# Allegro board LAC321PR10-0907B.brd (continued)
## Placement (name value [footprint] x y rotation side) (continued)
CC88  0.1U_0201_10V6K  [C_0201]  120.38 115.51 270 top
CC89  0.1U_0201_10V6K  [C_0201]  128.61 110.87 270 bottom
CC90  0.1U_0201_10V6K  [C_0201]  127.79 110.87 270 bottom
CC91  0.1U_0201_10V6K  [C_0201]  127.06 110.87 270 bottom
CC92  0.1U_0201_10V6K  [C_0201]  126.08 108.47 180 bottom
CC93  0.1U_0201_10V6K  [C_0201]  126.08 107.91 180 bottom
CC94  0.1U_0201_10V6K  [C_0201]  124.82 107.16 270 bottom
CC95  0.1U_0201_10V6K  [C_0201]  126.08 105.67 180 bottom
CC96  0.1U_0201_10V6K  [C_0201]  126.08 106.23 180 bottom
CC97  0.1U_0201_10V6K  [C_0201]  126.08 106.79 180 bottom
CC98  0.1U_0201_10V6K  [C_0201]  126.08 107.35 180 bottom
CC99  0.1U_0201_10V6K  [C_0201]  124.82 108.33 270 bottom
CC100  0.1U_0201_10V6K  [C_0201]  126.08 105.11 180 bottom
CC101  0.1U_0201_10V6K  [C_0201]  126.08 104.55 180 bottom
CC102  0.1U_0201_10V6K  [C_0201]  124.82 105.41 90 bottom
CC103  0.1U_0201_10V6K  [C_0201]  124.82 104.24 90 bottom
CC104  0.1U_0201_10V6K  [C_0201]  124.34 109.62 270 bottom
CC105  0.1U_0201_10V6K  [C_0201]  120.07 109.65 270 bottom
CC106  0.1U_0201_10V6K  [C_0201]  118.85 109.65 270 bottom
CC107  0.1U_0201_10V6K  [C_0201]  119.46 109.65 270 bottom
CC108  0.1U_0201_10V6K  [C_0201]  125.56 109.62 270 bottom
CC109  0.1U_0201_10V6K  [C_0201]  123.12 109.65 270 bottom
CC110  0.1U_0201_10V6K  [C_0201]  122.51 109.65 270 bottom
CC111  0.1U_0201_10V6K  [C_0201]  128.66 109.62 270 bottom
CC112  0.1U_0201_10V6K  [C_0201]  129.09 107.42 0 bottom
CC113  0.1U_0201_10V6K  [C_0201]  129.09 106.87 0 bottom
CC114  0.1U_0201_10V6K  [C_0201]  129.09 106.31 0 bottom
CC115  0.1U_0201_10V6K  [C_0201]  129.09 105.75 0 bottom
CC116  0.1U_0201_10V6K  [C_0201]  129.09 104.63 0 bottom
CC117  1U_0402_6.3V6K  [C_0402]  116.95 116.8 90 top
CC118  22U_0603_6.3V6M  [C_0603]  118.22 116.68 90 top
CC119  0.1U_0201_10V6K  [C_0201]  129.09 105.19 0 bottom
CC120  0.1U_0201_10V6K  [C_0201]  127.39 109.62 270 bottom
CC121  0.1U_0201_10V6K  [C_0201]  126.78 109.62 270 bottom
CC122  0.1U_0201_10V6K  [C_0201]  128 109.62 270 bottom
CC123  0.1U_0201_10V6K  [C_0201]  121.29 109.65 270 bottom
CC124  0.1U_0201_10V6K  [C_0201]  123.73 109.65 270 bottom
CC125  0.1U_0201_10V6K  [C_0201]  120.68 109.65 270 bottom
CC126  0.1U_0201_10V6K  [C_0201]  121.9 109.65 270 bottom
CC127  0.1U_0201_10V6K  [C_0201]  124.95 109.62 270 bottom
CC128  0.1U_0201_10V6K  [C_0201]  126.17 109.62 270 bottom
CC129  0.1U_0201_10V6K  [C_0201]  130.5 104.43 0 bottom
CC130  0.1U_0201_10V6K  [C_0201]  132.4 107.98 0 bottom
CC131  0.1U_0201_10V6K  [C_0201]  132.53 106.33 0 bottom
CC132  0.1U_0201_10V6K  [C_0201]  131.9 101.38 0 bottom
CC133  22U_0603_6.3V6M  [C_0603]  140.13 92.87 180 top
CC134  0.1U_0201_10V6K  [C_0201]  131.9 100.74 0 bottom
CC135  0.1U_0201_10V6K  [C_0201]  131.78 102.01 0 bottom
CC158  0.1U_0201_10V6K  [C_0201]  137.52 104.64 90 top
CC161  0.1U_0201_10V6K  [C_0201]  118.94 88.52 270 top
CC162  0.1U_0201_10V6K  [C_0201]  121.77 93.54 270 top
CC163  0.1U_0201_10V6K  [C_0201]  146.03 95.91 90 top
CC164  10P_0201_25V8  [C_0201]  139.02 110.32 180 top
CH3  15P_0402_50V8J  [C_0402]  141.89 97.43 270 top
CH4  15P_0402_50V8J  [C_0402]  141.71 99.17 270 top
CH5  1U_0402_6.3V6K  [C_0402]  139.91 116.82 270 top
CH6  1U_0402_6.3V6K  [C_0402]  142.58 119.85 90 top
CH7  10P_0402_50V8J  [C_0402]  139.05 119.72 90 top
CH8  8P_0402_50V8D  [C_0402]  139.08 118.78 270 top
CH11  0.22U_0201_6.3V6M  [C_0201]  135.81 92.59 90 top
CH12  0.22U_0201_6.3V6M  [C_0201]  136.38 92.59 90 top
CH13  0.22U_0201_6.3V6M  [C_0201]  133.84 93.8 90 top
CH14  0.22U_0201_6.3V6M  [C_0201]  134.41 93.8 90 top
CH16  0.22U_0201_6.3V6M  [C_0201]  135.12 93.86 90 top
CH17  0.22U_0201_6.3V6M  [C_0201]  135.69 93.87 90 top
CH19  0.22U_0201_6.3V6M  [C_0201]  134.51 92.61 90 top
CH20  0.22U_0201_6.3V6M  [C_0201]  135.08 92.6 90 top
CH21  0.1U_0201_10V6K  [C_0201]  131.03 94.34 90 top
CH22  0.1U_0201_10V6K  [C_0201]  131.6 94.34 90 top
CH23  0.22U_0201_6.3V6M  [C_0201]  197 92.11 180 bottom
CH24  0.22U_0201_6.3V6M  [C_0201]  197 92.74 180 bottom
CH25  0.22U_0201_6.3V6M  [C_0201]  197 89.57 180 bottom
CH26  0.22U_0201_6.3V6M  [C_0201]  197 90.2 180 bottom
CH27  0.1U_0201_10V6K  [C_0201]  130.54 92.58 90 top
CH28  0.1U_0201_10V6K  [C_0201]  131.15 92.58 90 top
CH32  0.1U_0201_10V6K  [C_0201]  212.07 135 90 top
CH35  0.22U_0201_6.3V6M  [C_0201]  132.45 93.95 90 top
CH36  0.22U_0201_6.3V6M  [C_0201]  133.03 93.96 90 top
CH39  0.1U_0201_10V6K  [C_0201]  138.25 128.57 0 top
CH40  0.1U_0201_10V6K  [C_0201]  139.19 122.06 0 top
CH41  0.1U_0201_10V6K  [C_0201]  141.55 110.4 0 bottom
CH42  0.1U_0201_10V6K  [C_0201]  140.79 112.81 0 bottom
CH43  0.1U_0201_10V6K  [C_0201]  164.27 108.9 0 top
CH44  0.1U_0201_10V6K  [C_0201]  241.98 105.84 90 top
CH45  0.1U_0201_10V6K  [C_0201]  242.55 105.84 90 top
CH46  0.1U_0201_10V6K  [C_0201]  144.34 119.54 0 top
CH47  0.1U_0201_10V6K  [C_0201]  130.26 84.7 180 top
CH48  0.1U_0201_10V6K  [C_0201]  130.26 84.15 180 top
CH49  0.1U_0201_10V6K  [C_0201]  144.51 125.29 0 top
CH50  0.1U_0201_10V6K  [C_0201]  139.87 122.77 180 top
CLRP3  SHORT PADS  [SHORTPADS]  160.36 132.8 270 top
CLRP4  SHORT PADS  [SHORTPADS]  142.6 118.27 90 top
CR1  1U_0201_6.3V6M  [C_0201]  23.43 80.59 0 top
CR2  10U_0402_6.3V6M  [C_0402]  28.81 84.36 180 top
CR3  0.1U_0201_10V6K  [C_0201]  28.81 83.6 180 top
CR4  0.1U_0201_10V6K  [C_0201]  29.94 84.44 270 top
CR5  0.1U_0201_10V6K  [C_0201]  27.15 83.85 90 top
CR6  4.7U_0402_6.3V6M  [C_0402]  26.38 83.69 90 top
CR7  0.1U_0201_10V6K  [C_0201]  27.15 75.55 270 top
CR8  2.2P_0402_50V8C~D  [C_0402]  23.72 82.04 90 top
CR11  4.7U_0402_6.3V6M  [C_0402]  26.4 75.62 270 top
CR14  10U_0402_6.3V6M  [C_0402]  21.82 82.71 90 top
CR15  0.1U_0201_10V6K  [C_0201]  22.55 82.65 90 top
CR16  1U_0201_6.3V6M  [C_0201]  23.43 76.15 0 top
CR17  4.7U_0402_6.3V6M  [C_0402]  21.82 86.06 90 top
CR18  0.1U_0201_10V6K  [C_0201]  21.7 85.29 270 top
CR19  6.8P_0201_25V8B  [C_0201]  23.43 76.78 0 top
CR20  6.8P_0201_25V8B  [C_0201]  23.43 78.05 0 top
CR21  6.8P_0201_25V8B  [C_0201]  23.43 79.37 0 top
CR22  0.1U_0201_10V6K  [C_0201]  23.72 84.44 270 top
CR23  6.8P_0201_25V8B  [C_0201]  24.99 84.44 270 top
CT1  10U_0603_25V6M  [C_0603]  15.49 37.03 270 top
CT2  10U_0603_25V6M  [C_0603]  13.63 18.45 0 top
CT3  0.1U_0402_25V6  [C_0402]  9.02 23.99 270 top
CT4  0.1U_0402_25V6  [C_0402]  10.8 21.32 90 top
D1  -  [BAT54CW-7-F_SOT323-3]  174.43 104.12 0 top
D2  -  [BAT54CW-7-F_SOT323-3]  176.84 102.22 180 top
D3  -  [BAT54CW-7-F_SOT323-3]  179.25 102.22 180 top
D4  -  [PJSOT24CW_SOT323-3]  240.26 122.65 180 top
D5  -  [PJSOT24CW_SOT323-3]  222.64 124.39 180 top
D6  -  [AOZ8904CIL_SOT23-6]  25.67 73.12 180 top
D8  -  [BAT54A-7-F_SOT23-3]  38.19 11.46 90 top
D10  -  [BAT54CW-7-F_SOT323-3]  232.2 136.48 270 top
D11  -  [BAT54CW-7-F_SOT323-3]  37.51 95.26 0 top
D17  -  [PESD24VS2UT_SOT23-3]  92.08 90.46 180 top
D22  -  [SDMK0340L-7-F_SOD323-2]  229.17 133.87 180 top
D23  -  [SDMK0340L-7-F_SOD323-2]  204.58 109.22 90 top
D74  -  [TPD2EUSB30DRTR_SOT3]  126.24 87.58 270 top
D75  ESD8011MUT5G X3DFN2  [ESD101-B1-02ELS_TSSLP-2-4-2]  12.45 36.8 90 bottom
D76  ESD8011MUT5G X3DFN2  [ESD101-B1-02ELS_TSSLP-2-4-2]  12.36 31.41 225 bottom
D77  ESD8011MUT5G X3DFN2  [ESD101-B1-02ELS_TSSLP-2-4-2]  13.41 36.8 90 bottom
D78  ESD8011MUT5G X3DFN2  [ESD101-B1-02ELS_TSSLP-2-4-2]  11.73 32.17 225 bottom
D79  ESD8011MUT5G X3DFN2  [ESD101-B1-02ELS_TSSLP-2-4-2]  10.61 35.78 90 bottom
D80  ESD8011MUT5G X3DFN2  [ESD101-B1-02ELS_TSSLP-2-4-2]  12.64 29.06 225 bottom
D81  ESD8011MUT5G X3DFN2  [ESD101-B1-02ELS_TSSLP-2-4-2]  11.57 35.78 90 bottom
D82  ESD8011MUT5G X3DFN2  [ESD101-B1-02ELS_TSSLP-2-4-2]  12 29.83 225 bottom
D83  ESD8011MUT5G X3DFN2  [ESD101-B1-02ELS_TSSLP-2-4-2]  11.78 22.51 90 bottom
D84  ESD8011MUT5G X3DFN2  [ESD101-B1-02ELS_TSSLP-2-4-2]  14.17 24.77 270 bottom
D85  ESD8011MUT5G X3DFN2  [ESD101-B1-02ELS_TSSLP-2-4-2]  12.77 22.51 90 bottom
D86  ESD8011MUT5G X3DFN2  [ESD101-B1-02ELS_TSSLP-2-4-2]  13.18 24.77 270 bottom
D87  ESD8011MUT5G X3DFN2  [ESD101-B1-02ELS_TSSLP-2-4-2]  10.37 24.39 90 bottom
D88  ESD8011MUT5G X3DFN2  [ESD101-B1-02ELS_TSSLP-2-4-2]  15.77 23.39 270 bottom
D89  ESD8011MUT5G X3DFN2  [ESD101-B1-02ELS_TSSLP-2-4-2]  11.33 24.39 90 bottom
D90  ESD8011MUT5G X3DFN2  [ESD101-B1-02ELS_TSSLP-2-4-2]  14.78 23.39 270 bottom
D95  -  [L06ESDU5V0CE2_SOD-882-2]  72.88 148.63 90 top
D100  -  [SDMK0340L-7-F_SOD323-2]  32.86 32.85 90 top
D101  -  [SDMK0340L-7-F_SOD323-2]  31.62 52.78 90 top
D406  -  [RB520SM-30T2R_EMD2-2]  175.41 115.82 180 top
D407  ESD8011MUT5G X3DFN2  [ESD101-B1-02ELS_TSSLP-2-4-2]  13.6 33.78 90 top
D408  ESD8011MUT5G X3DFN2  [ESD101-B1-02ELS_TSSLP-2-4-2]  14.31 34.16 270 top
D409  ESD8011MUT5G X3DFN2  [ESD101-B1-02ELS_TSSLP-2-4-2]  13.84 29.29 180 top
D410  ESD8011MUT5G X3DFN2  [ESD101-B1-02ELS_TSSLP-2-4-2]  13.46 30.01 0 top
D411  ESD8011MUT5G X3DFN2  [ESD101-B1-02ELS_TSSLP-2-4-2]  13.46 28.57 0 top
D412  ESD8011MUT5G X3DFN2  [ESD101-B1-02ELS_TSSLP-2-4-2]  13.49 25.83 270 top
D413  ESD8011MUT5G X3DFN2  [ESD101-B1-02ELS_TSSLP-2-4-2]  13.49 26.46 90 top
D414  ESD8011MUT5G X3DFN2  [ESD101-B1-02ELS_TSSLP-2-4-2]  13.49 27.49 90 top
D415  ESD8011MUT5G X3DFN2  [ESD101-B1-02ELS_TSSLP-2-4-2]  15.87 18.02 90 top
D416  ESD8011MUT5G X3DFN2  [ESD101-B1-02ELS_TSSLP-2-4-2]  16.58 18.4 270 top
D417  ESD8011MUT5G X3DFN2  [ESD101-B1-02ELS_TSSLP-2-4-2]  15.64 15.41 270 top
D418  ESD8011MUT5G X3DFN2  [ESD101-B1-02ELS_TSSLP-2-4-2]  14.93 15.03 90 top
D419  ESD8011MUT5G X3DFN2  [ESD101-B1-02ELS_TSSLP-2-4-2]  14.12 22.04 180 top
D420  ESD8011MUT5G X3DFN2  [ESD101-B1-02ELS_TSSLP-2-4-2]  13.74 21.32 0 top
D421  ESD8011MUT5G X3DFN2  [ESD101-B1-02ELS_TSSLP-2-4-2]  14.17 15.17 270 top
D422  ESD8011MUT5G X3DFN2  [ESD101-B1-02ELS_TSSLP-2-4-2]  13.46 15.17 270 top
D423  ESD207-B1-02ELE6327 TSLP-2-19  [ESD101-B1-02ELS_TSSLP-2-4-2]  191.66 96.76 0 top
D424  ESD218-B1-02ELS TSSLP-2-4  [ESD3V3S1B-02LS_PG-TSSLP-2-1-2]  15.45 37.92 0 top
D425  ESD218-B1-02ELS TSSLP-2-4  [ESD3V3S1B-02LS_PG-TSSLP-2-1-2]  13.67 22.83 0 top
DA1  -  [ESD207-B1-02EL_TSLP-2-19-2]  23.09 11.9 90 top
DA2  -  [ESD207-B1-02EL_TSLP-2-19-2]  15.23 96.93 90 top
DA3  -  [ESD207-B1-02EL_TSLP-2-19-2]  19.48 9.94 0 top
DA4  -  [ESD207-B1-02EL_TSLP-2-19-2]  21.83 9.94 180 top
DA5  -  [TVNST52302AB0_SOT523-3]  246.58 134.32 90 top
DA6  -  [TVNST52302AB0_SOT523-3]  23.36 92.9 270 top
DA7  -  [PJSOT24CW_SOT323-3]  37.34 25.28 180 top
DA8  -  [ESD207-B1-02EL_TSLP-2-19-2]  23.09 10.52 270 top
DH5  -  [RB751S40T1G_SOD523-2]  26.84 7.02 180 top
DH6  -  [RB751S40T1G_SOD523-2]  231.12 107.59 0 top
DI4  -  [TVNST52302AB0_SOT523-3]  186.48 96.3 90 top
DI5  -  [TVNST52302AB0_SOT523-3]  189.44 96.2 90 top
DI6  -  [PESD24VS2UT_SOT23-3]  19.84 55.74 180 top
DI7  BAT54A-7-F_SOT23-3  [PESD24VS2UT_SOT23-3]  36.18 40.01 0 top
FD1  -  [FIDUCIAL_C40M80]  249.09 143.39 0 top
FD2  -  [FIDUCIAL_C40M80]  14.76 11.07 0 top
FD3  -  [FIDUCIAL_C40M80]  14.84 11.55 90 bottom
FD4  -  [FIDUCIAL_C40M80]  243.57 147.89 90 bottom
H1  -  [H_4P6]  37.5 3.55 0 top
H2  -  [H_4P6]  194.5 83.55 90 top
H4  -  [H_4P6]  13.1 3.55 0 top
H5  -  [H_4P6]  43 147.55 0 top
H6  -  [H_4P6]  233.5 147.55 0 top
H7  -  [H_4P6]  7.5 108.05 0 top
H8  -  [H_1P2]  143.1 104.62 90 top
H9  -  [H_1P2]  104.1 103.62 90 top
H10  -  [H_1P3X2P3]  195.5 95.9 90 top
H11  -  [H_1P3]  3 95.9 0 top
H13  -  [H_2P0X0P4N]  160.5 138.5 0 top
H14  -  [H_2P0X0P4N]  147.7 126.11 90 top
H15  -  [H_2P0X0P4N]  103 131.05 0 top
H16  -  [H_2P0X0P4N]  63.95 126.31 90 top
H17  -  [H_2P0X0P4N]  68.15 130.7 0 top
H18  -  [H_2P0X0P4N]  197.49 103.09 90 top
H19  -  [H_2P0X0P4N]  143 131.05 0 top
H20  -  [H_2P0X0P4N]  92.85 130.7 0 top
H21  -  [H_2P0X0P4N]  152.5 131.55 0 top
H22  -  [H_2P0X0P4N]  181.5 138.5 0 top
H23  -  [H_4P6]  41.25 78.33 0 top
H24  -  [H_5P2]  139.1 78.33 0 top
H25  -  [H_2P0X0P4N]  40.46 58.96 270 top
H26  -  [H_2P0X0P4N]  12.24 10.66 270 top
H27  -  [H_2P0X0P4N]  4.67 45.42 270 top
H28  -  [H_2P0X0P4N]  20.37 62.59 270 top
H29  -  [H_2P0X0P4N]  56.85 83.74 0 top
H30  -  [H_2P0X0P4N]  49.64 150.07 0 top
H31  -  [H_2P0X0P4N]  40.81 142.09 0 top
H32  -  [H_2P0X0P4N]  241.88 140.61 0 top
H33  -  [H_2P0X0P4N]  242.21 113.41 0 top
H34  -  [H_2P0X0P4N]  199.26 113.41 0 top
J3  HRS_DF40C-24DS-0P4V(51)  [HRS_DF40C-24DS-0P4V-51_24P-T]  129.64 133.64 180 top
JANT1  BELLW_10093-1021  [BELLW_10093-1021_4P]  76.5 148.02 180 top
JAPS2  ACES_50506-01841-P01  [ACES_50506-01841-P01_18P]  224.77 143.67 180 top
JAR1  ACES_50281-00601-001  [ACES_50281-00601-001_6P]  34.02 47.07 90 top
JBAT100  ACES_50278-01001-001  [ACES_50278-01001-001_10P]  149.8 90.74 0 top
JCAM2  STARC_111D10-000000-G4-R  [STARC_111D10-000000-G4-R_10P]  99.34 132.71 180 top
JCR1  T-SOL_158-1000902614  [T-SOL_158-1000902614_23P-T]  17.15 83.22 270 top
JDEBUG1  ACES_50521-01041-P01  [ACES_50521-01041-P01_10P]  235.27 111.47 0 top
JDEG1  ACES_50521-01041-P01  [ACES_50521-01041-P01_10P]  211.73 146.22 180 top
JDMIC1  HRS_DF40B-12DS-0P4V(51)  [HRS_DF40B-12DS-0P4V-51_12P-T]  86.08 136.63 0 top
JHP1  ACES_50521-01041-P01  [ACES_50521-01041-P01_10P]  19.21 5.8 0 top
JITOUCH  ACES_50521-01041-P01  [ACES_50521-01041-P01_10P]  164.41 91.2 180 bottom
JLPDE1  ACES_50521-01041-P01  [ACES_50521-01041-P01_10P]  210.76 111.33 0 top
JLVDS1  ACES_50398-05071-001  [ACES_50398-05071-001_50P-T]  192.65 93.96 180 top
JNGFF1  LOTES_APCI0133-P001A  [LOTES_APCI0133-P001A_67P-T]  32.8 102.36 180 top
JNGFF2  LOTES_APCI0170-P001A  [LOTES_APCI0170-P001A_75P-T]  199.29 83.73 90 top
JNGFF3  LOTES_APCI0114-P001A  [LOTES_APCI0114-P001A_67P]  246.39 108.37 90 top
JP1  HRS_DF37NC-30DS-0P4V(51)  [HRS_DF37NC-30DS-0P4V-51_30P-T]  142.71 136.71 0 top
JPA1  0_0402_5%~D  [R0402_0OHM]  21.05 16.3 0 top
JPA2  0_0402_5%~D  [R0402_0OHM]  20.05 16.04 270 top
JPA3  0_0402_5%~D  [R0402_0OHM]  38.21 20.18 270 top
JPA4  0_0402_5%~D  [R_0402]  112.19 127.83 0 top
JPB1  ACES_50506-00641-P01  [ACES_50506-00641-P01_6P]  250.7 138.85 90 top
JPOGO  PANAS_AXT580124  [PANAS_AXT580124_80P-T]  107.7 86.23 0 top
JRTC1  ACES_50278-00201-001  [ACES_50278-00201-001_2P]  238.75 145.72 90 top
JSER  ACES_50506-01841-P01  [ACES_50506-01841-P01_18P]  220.65 138.59 0 bottom
JSIM1  JAE_SF56S006V4A  [JAE_SF56S006V4A_6P-T]  5.41 66.71 270 top
JSPI1  ACES_50696-0200M-P01  [ACES_50696-0200M-P01_20P]  214.28 140.64 0 bottom
JSPK1  ACES_50208-00201-P03  [ACES_50208-00201-P03_2P]  251.6 132.5 90 top
JSPK2  ACES_50208-00201-P03  [ACES_50208-00201-P03_2P]  10.8 96.89 270 top
JUSBC1  JAE_DX07B024XJ1  [JAE_DX07B024XJ1_24P-T]  8.66 33.26 270 top
JUSBC2  JAE_DX07B024XJ1  [JAE_DX07B024XJ1_24P-T]  8.66 19.26 270 top
JVB1  ACES_50208-00201-P03  [ACES_50208-00201-P03_2P]  28.95 5.5 0 top
JVOL1  ACES_50521-00541-P01  [ACES_50521-00541-P01_5P]  4.45 99.26 180 top
JXDP2  SAMTE_BSH-030-01-L-D-A-TR  [SAMTE_BSH-030-01-L-D-A-TR_60P-S]  108.05 91.8 0 bottom
L1  BLM15AX700SN1D_2P  [MURAT_BLM15AX100SN1D_2P]  26.67 10.7 180 top
L2  BLM15AX700SN1D_2P  [MURAT_BLM15AX100SN1D_2P]  26.67 11.72 180 top
L3  BLM15PX330SN1D_2P  [MURAT_BLM15PX330SN1D_2P]  21.32 11.97 0 top
L4  BLM15PX330SN1D_2P  [MURAT_BLM15PX330SN1D_2P]  20.1 11.97 180 top
L17  1UH_1269AS-H-1R0M-P2_2.5A_20%  [TOKO_1269AS-H-1R0M-P2_2P]  191.26 146.67 0 top
L19  FBMA-L11-160808-800LMT_0603  [KC_FBMA-L11-160808-800LMT_2P]  231.37 132.48 270 top
L21  10NH_LQG15HS10NJ02D_5%_0402  [MURAT_LQG15HS10NJ02D_2P]  72.88 147.57 270 top
L23  DLW21HN900HQ2L_4P  [MURAT_DLW21HN900HQ2L_4P]  106.32 127.58 90 top
L24  DLW21HN900HQ2L_4P  [MURAT_DLW21HN900HQ2L_4P]  143.7 127.53 90 top
L25  DLW21HN900HQ2L_4P  [MURAT_DLW21HN900HQ2L_4P]  194.46 99.43 0 top
L26  DLW21HN900HQ2L_4P  [MURAT_DLW21HN900HQ2L_4P]  239.24 120.58 0 top
L27  CMMI21T-900Y-N_4P  [CHILI_CMMI21T-900Y-N_4P]  16.12 98.13 0 top
L28  DLW21HN900HQ2L_4P  [MURAT_DLW21HN900HQ2L_4P]  108.23 127.58 90 top
L29  DLW21HN900HQ2L_4P  [MURAT_DLW21HN900HQ2L_4P]  104.42 127.58 90 top
L30  DLW21HN900HQ2L_4P  [MURAT_DLW21HN900HQ2L_4P]  158.74 134.2 180 top
L31  DLW21HN900HQ2L_4P  [MURAT_DLW21HN900HQ2L_4P]  145.59 127.52 90 top
L32  DLW21HN900HQ2L_4P  [MURAT_DLW21HN900HQ2L_4P]  158.74 132.3 180 top
L33  DLW21HN900HQ2L_4P  [MURAT_DLW21HN900HQ2L_4P]  158.74 136.11 180 top
L57  MCF12102G900-T_4P  [TAIYO_MCF12102G900-T_4P]  172.66 96.8 270 top
L58  MCF12102G900-T_4P  [TAIYO_MCF12102G900-T_4P]  174.18 96.8 270 top
L59  MCF12102G900-T_4P  [TAIYO_MCF12102G900-T_4P]  169.67 96.8 270 top
L60  MCF12102G900-T_4P  [TAIYO_MCF12102G900-T_4P]  171.17 96.8 270 top
L61  MCF12102G900-T_4P  [TAIYO_MCF12102G900-T_4P]  175.58 96.8 270 top
L62  WCM-2012HS-900T_4P  [KC_WCM-2012HS-900T_4P]  29.95 42.92 90 top
L63  0.6UH_MND-04ABIR60M-XGL_20%  [MAG_MND-04ABIR60M-XGL_2P]  19.57 26.69 180 top
L64  1UH +-20% LQM18PN1R0MFHD  [R_0603]  18.87 22.02 90 top
LA1  BLM21PG600SN1D_2P  [MURAT_BLM21PG600SN1D_2P]  36.62 18.97 90 top
LA2  0.01_0603_1%  [R_0603]  36.81 23.02 180 top
LA3  0.01_0603_1%  [R_0603]  36.81 21.75 180 top
LA4  0.01_0603_1%  [R_0603]  26.07 24.47 90 top
LA18  0_0603_5%  [R_0603]  211.63 118.78 0 top
LA19  0_0603_5%  [R_0603]  211.63 122.84 0 top
LA20  0_0603_5%  [R0603_0OHM]  209.72 125.38 0 top
LA21  0_0603_5%  [R0603_0OHM]  209.72 124.11 0 top
LA22  0_0603_5%  [R0603_0OHM]  207.14 116.95 180 top
LA23  0_0603_5%  [R0603_0OHM]  207.14 115.73 180 top
LR1  WCM-2012HS-900T_4P  [KC_WCM-2012HS-900T_4P]  31.36 77.35 90 top
LT1  HCB2012KF-121T50_2P  [TAI-T_HCB2012KF-121T50_2P]  10.42 36.45 90 top
LT2  HCB2012KF-121T50_2P  [TAI-T_HCB2012KF-121T50_2P]  13.79 13.62 0 top
LT105  HCB2012KF-121T50_0805  [TAI-T_HCB2012KF-121T50_2P]  16.15 49.85 0 top
LT106  HCB2012KF-121T50_0805  [TAI-T_HCB2012KF-121T50_2P]  31.6 49.29 270 top
MC1  10P_0402_50V8J  [C_0402]  145.35 118.78 180 top
MC2  680P_0402_50V7K  [C_0402]  181.13 95.92 90 top
MD1  -  [TVWDF1004AD0_DFN9]  119 129.25 180 top
MD4  -  [RCLAMP0524PATCT_SLP2510P8-10-9]  103.43 89.05 270 top
MD6  -  [RCLAMP0524PATCT_SLP2510P8-10-9]  143.64 87.33 90 top
ML1  DLW21HN900HQ2L_4P  [MURAT_DLW21HN900HQ2L_4P]  237.76 116.65 0 top
ML2  DLW21HN900HQ2L_4P  [MURAT_DLW21HN900HQ2L_4P]  38.11 104.22 180 top
ML3  CMMI21T-670Y-N  [MURAT_DLW21SN670HQ2L_4P]  117.86 125.04 90 top
ML4  CMMI21T-670Y-N  [MURAT_DLW21SN670HQ2L_4P]  119.75 124.72 90 top
ML5  MCM1012B900F06BP_4P  [INPAQ_MCM1012B900F06BP_4P]  129.43 88.54 180 top
ML6  MCM1012B900F06BP_4P  [INPAQ_MCM1012B900F06BP_4P]  14.2 32.64 270 top
ML7  MCM1012B900F06BP_4P  [INPAQ_MCM1012B900F06BP_4P]  15.22 16.55 180 top
ML9  DLW21HN900HQ2L_4P  [MURAT_DLW21HN900HQ2L_4P]  180.87 99.68 0 top
ML11  CMMI21T-670Y-N  [MURAT_DLW21SN670HQ2L_4P]  18.97 98.14 90 top
ML12  CMMI21T-670Y-N  [MURAT_DLW21SN670HQ2L_4P]  38.11 102.29 180 top
ML13  CMMI21T-670Y-N  [MURAT_DLW21SN670HQ2L_4P]  242.66 107.48 90 top
ML14  LPF0805F2SF-900T04  [SW_WCM2012F2S_4P]  233.17 111.08 270 top
ML15  CMMI21T-670Y-N  [MURAT_DLW21SN670HQ2L_4P]  243.62 111.74 180 top
NOREF  -  []  43 147.55 0 top
NOREF#2  -  []  233.5 147.55 0 top
NOREF#3  -  []  143.1 104.62 0 top
NOREF#4  -  []  168.88 66.19 0 top
NOREF#5  -  []  143.1 104.62 0 top
NOREF#6  -  []  104.1 104.62 0 top
NOREF#7  -  []  57.21 79.48 0 top
NOREF#8  -  []  115.74 32.41 0 top
NOREF#9  -  []  87.99 193.45 0 top
NOREF#10  -  []  41.25 78.33 0 top
NOREF#11  -  []  102.12 79.38 0 top
NOREF#12  -  []  3 95.9 0 top
NOREF#13  -  []  7.5 108.05 0 top
NOREF#14  -  []  104.1 103.62 0 top
NOREF#15  -  []  188.32 124.75 180 bottom
NOREF#16  -  []  141.29 121.13 180 bottom
NOREF#17  -  []  7.7 66.99 180 bottom
NOREF#18  -  []  66.22 105.67 180 bottom
NOREF#19  -  []  107.65 116.9 90 bottom
NOREF#20  -  []  90.6 83.03 180 bottom
PC100  1000P_0402_50V7K  [C_0402]  43.36 104.3 0 top
PC101  0.01U_0402_25V7K  [C_0402]  43.39 103.12 0 top
PC102  1000P_0402_50V7K  [C_0402]  46.69 138.16 90 top
PC103  1000P_0402_50V7K  [C_0402]  41.29 137.83 90 top
PC105  0.01U_0402_25V7K  [C_0402]  47.01 103.27 180 top
PC106  1000P_0402_50V7K  [C_0402]  47.01 104.16 180 top
PC107  0.1U_0402_25V6  [C_0402]  78.59 86.88 90 top
PC108  1000P_0402_50V7K  [C_0402]  84.74 89.57 0 top
PC109  2200P_0402_50V7K  [C_0402]  84.74 90.46 0 top
PC110  0.1U_0402_25V6  [C_0402]  42.18 106.45 180 top
PC111  10U_0603_25V6M  [C_0603]  43.07 106.27 0 top
PC112  0.1U_0402_25V6  [C_0402]  47.01 105.05 180 top
PC113  10U_0603_25V6M  [C_0603]  46.96 106.13 180 top
PC114  100P_0402_50V8J  [C_0402]  43.39 102.23 0 top
PC115  100P_0402_50V8J  [C_0402]  43.31 105.19 0 top
PC116  100P_0402_50V8J  [C_0402]  44.96 140.55 0 top
PC117  220P_0402_50V7K  [C_0402]  41.27 139.61 0 top
PC118  100P_0402_50V8J  [C_0402]  47.01 102.38 180 top
PC119  100P_0402_50V8J  [C_0402]  50.67 106.97 270 top
PC120  0.01U_0402_25V7K  [C_0402]  46.49 135.29 90 top
PC121  0.022U_0402_25V7K  [C_0402]  46.09 108.71 90 top
PC122  0.022U_0402_25V7K  [C_0402]  41.32 117.85 270 top
PC123  0.022U_0402_25V7K  [C_0402]  51.57 107.78 90 top
PC124  0.022U_0402_25V7K  [C_0402]  50.64 114.22 270 top
PC125  220P_0402_50V7K  [C_0402]  43.07 132.46 90 top
PC126  100P_0402_50V8J  [C_0402]  44.94 133.37 270 top
PC127  0.1U_0402_25V6  [C_0402]  49.14 124.56 180 top
PC128  0.1U_0402_25V6  [C_0402]  48.22 127.2 0 top
PC129  0.01U_0402_25V7K  [C_0402]  41.31 133.46 270 top
PC130  0.1U_0402_25V6  [C_0402]  42.2 124.6 180 top
PC131  0.01U_0402_25V7K  [C_0402]  43.62 85.97 90 top
PC132  1U_0402_16V6K  [C_0402]  42.7 86.89 270 top
PC133  1U_0603_25V6  [C_0603]  30.97 66.45 0 top
PC134  1U_0402_16V6K  [C_0402]  29.32 70.9 270 top
PC135  10U_0603_25V6M  [C_0603]  34.22 70.65 270 top
PC200  1U_0603_25V6  [C_0603]  48.64 140.39 0 top
PC201  1U_0402_16V6K  [C_0402]  50.74 142.5 180 top
PC202  0.01U_0402_25V7K  [C_0402]  65.32 140.98 180 top
PC203  1U_0402_16V6K  [C_0402]  94.62 96.22 90 top
PC204  1U_0603_25V6  [C_0603]  92.73 96.5 180 top
PC205  0.01U_0402_25V7K  [C_0402]  79.1 129.27 270 top
PC206  0.1U_0402_25V6  [C_0402]  81.01 129.19 270 top
PC207  0.01U_0402_25V7K  [C_0402]  62.27 145.35 270 top
PC208  0.1U_0402_25V6  [C_0402]  61.33 146.78 90 top
PC209  0.1U_0402_25V6  [C_0402]  77.7 122.41 270 top
PC211  0.01U_0402_25V7K  [C_0402]  62.59 140.94 0 top
PC212  0.01U_0402_25V7K  [C_0402]  61.98 141.83 0 top
PC213  1U_0402_16V6K  [C_0402]  51.76 141.55 270 top
PC214  0.01U_0402_25V7K  [C_0402]  66.27 124.87 90 top
PC215  0.01U_0402_25V7K  [C_0402]  52.11 147.76 90 top
PC217  0.01U_0402_25V7K  [C_0402]  66.27 122.16 270 top
PC218  0.01U_0402_25V7K  [C_0402]  70.54 119.54 180 top
PC219  0.1U_0402_25V6  [C_0402]  77.31 128.3 0 top
PC220  0.1U_0402_25V6  [C_0402]  50 148.62 0 top
PC221  0.1U_0201_10V6K  [C_0201]  177.36 105.91 0 top
PC222  1U_0402_6.3V6K  [C_0402]  69.58 122.03 270 top
PC223  0.022U_0402_25V7K  [C_0402]  72.4 138.64 90 top
PC224  0.022U_0402_25V7K  [C_0402]  67.11 136.18 180 top
PC225  0.022U_0402_25V7K  [C_0402]  61.58 136.1 90 top
PC226  0.022U_0402_25V7K  [C_0402]  66.49 134.22 270 top
PC227  0.1U_0402_25V6  [C_0402]  72.22 141.28 270 top
PC228  0.22U_0201_6.3V6K  [C_0201]  66.19 127.29 180 top
PC229  0.22U_0201_6.3V6K  [C_0201]  70.35 127.26 0 top
PC230  1000P_0402_50V7K  [C_0402]  68.99 123.02 180 top
PC231  1000P_0402_50V7K  [C_0402]  72.85 125.87 90 top
PC232  0.1U_0402_25V6  [C_0402]  67.11 135.29 180 top
PC233  0.1U_0402_25V6  [C_0402]  67.53 141.85 270 top
PC300  2.2U_0402_6.3V6K  [C_0402]  167.85 104.94 270 top
PC400  10U_0805_25V6K  [C_0805]  55.84 120.06 90 top
PC401  0.1U_0402_25V6  [C_0402]  57.64 118.22 0 top
PC402  2200P_0402_50V7K  [C_0402]  53.73 114.71 180 top
PC403  10U_0805_25V6K  [C_0805]  51.81 119.43 90 top
PC404  10U_0805_25V6K  [C_0805]  57.37 119.5 0 top
PC405  10U_0805_25V6K  [C_0805]  57.37 121.2 0 top
PC406  10U_0805_25V6K  [C_0805]  53.6 119.43 90 top
PC407  10U_0805_25V6K  [C_0805]  53.84 117.74 180 top
PC408  10U_0805_25V6K  [C_0805]  53.82 116.01 180 top
PC409  1U_0603_25V6K  [C_0603]  55.45 133.54 0 top
PC410  0.1U_0402_25V6  [C_0402]  55.78 132.23 0 top
PC411  0.1U_0402_25V6  [C_0402]  57.56 132.23 0 top
PC414  10U_0603_25V6M  [C_0603]  59.86 103.67 0 top
PC415  10U_0603_25V6M  [C_0603]  59.86 106.33 0 top
PC418  1U_0603_10V6K  [C_0603]  59.35 127.03 0 top
PC419  10U_0603_25V6M  [C_0603]  59.86 104.94 0 top
PC421  1U_0603_25V6K  [C_0603]  60.75 130.84 180 top
PC422  0.1U_0402_25V6  [C_0402]  51.97 132.37 0 top
PC423  0.047U_0603_25V7M  [C_0603]  60.75 129.57 180 top
PC424  10U_0603_25V6M  [C_0603]  72.62 86.58 270 top
PC425  10U_0805_25V6K  [C_0805]  69.74 85.5 0 top
PC426  10U_0805_25V6K  [C_0805]  68.52 85.5 180 top
PC427  100P_0402_50V8J  [C_0402]  51.11 132.37 180 top
PC428  100P_0402_50V8J  [C_0402]  51.11 130.59 180 top
PC429  0.1U_0402_25V6  [C_0402]  58.53 124.62 180 top
PC430  0.1U_0402_25V6  [C_0402]  56.7 124.62 180 top
PC431  0.1U_0402_25V6  [C_0402]  55.78 123.71 270 top
PC432  330P_0603_50V8  [C_0603]  59.64 109.12 0 top
PC433  1U_0603_25V6K  [C_0603]  53.7 124.56 270 top
PC434  10U_0805_25V6K  [C_0805]  76.74 90.83 90 top
PC436  10U_0603_25V6M  [C_0603]  54.18 103.65 270 top
PC437  10U_0603_25V6M  [C_0603]  55.45 103.65 270 top
PC438  10U_0603_25V6M  [C_0603]  57.89 103.65 270 top
PC439  10U_0603_25V6M  [C_0603]  56.67 103.65 270 top
PC440  10U_0603_25V6M  [C_0603]  59.86 107.55 0 top
PC441  10U_0603_25V6M  [C_0603]  52.97 103.64 270 top
PC442  33U_B3_16VM_R45M  [C_B3]  70.78 90.62 90 top
PC443  33U_B3_16VM_R45M  [C_B3]  74.03 90.62 90 top
PC444  33U_B3_16VM_R45M  [C_B3]  67.53 90.59 90 top
PC500  1U_0402_16V6K  [C_0402]  161.02 122.33 270 top
PC501  10U_0603_25V6M  [C_0603]  174.92 125.95 90 top
PC502  0.1U_0402_25V7K  [C_0402]  172.99 126.08 90 top
PC503  10U_0805_25V6K  [C_0805]  161.8 113.73 270 top
PC504  0.1U_0402_25V7K  [C_0402]  160.38 113.52 270 top
PC505  1U_0402_16V6K  [C_0402]  175.74 129 0 top
PC506  0.1U_0402_25V6  [C_0402]  164.06 117 90 top
PC507  0.1U_0402_25V6  [C_0402]  175.88 123.73 0 top
PC508  22U_0603_6.3V6M  [C_0603]  151.81 117.51 180 top
PC509  22U_0603_6.3V6M  [C_0603]  155.06 118.11 0 top
PC510  22U_0603_6.3V6M  [C_0603]  151.81 116.24 180 top
PC511  22U_0603_6.3V6M  [C_0603]  151.81 114.97 180 top
PC512  22U_0603_6.3V6M  [C_0603]  153.78 112.05 0 top
PC513  22U_0603_6.3V6M  [C_0603]  182.77 123.55 0 top
PC514  22U_0603_6.3V6M  [C_0603]  182.77 121.01 0 top
PC515  22U_0603_6.3V6M  [C_0603]  182.77 122.28 0 top
PC516  1000P_0603_50V7K  [C_0603]  179.05 126.78 180 top
PC517  1000P_0603_50V7K  [C_0603]  158.1 121.06 0 top
PC518  0.047U_0402_25V7K  [C_0402]  159.05 123.03 90 top
PC519  10U_0603_25V6M  [C_0603]  164.64 130.34 180 top
PC520  0.1U_0402_25V7K  [C_0402]  167.67 129.7 0 top
PC521  10U_0805_25V6K  [C_0805]  179.81 133.6 270 top
PC522  0.1U_0402_25V7K  [C_0402]  180.07 135.54 90 top
PC523  0.1U_0402_25V6  [C_0402]  179.05 130.72 0 top
PC524  0.1U_0402_25V6  [C_0402]  164.17 129.12 270 top
PC525  10U_0805_25V6K  [C_0805]  187.56 120.39 270 top
PC526  10U_0805_25V6K  [C_0805]  189.34 120.39 270 top
PC527  10U_0805_25V6K  [C_0805]  191.12 120.39 270 top
PC528  22U_0603_6.3V6M  [C_0603]  168.89 133.51 0 top
PC529  22U_0603_6.3V6M  [C_0603]  170.22 135.29 90 top
PC530  22U_0603_6.3V6M  [C_0603]  169.02 135.29 90 top
PC531  22U_0603_6.3V6M  [C_0603]  187.37 127.41 0 top
PC532  22U_0603_6.3V6M  [C_0603]  187.88 126.14 0 top
PC533  22U_0603_6.3V6M  [C_0603]  186.86 128.68 0 top
PC534  22U_0603_6.3V6M  [C_0603]  187.05 129.83 90 top
PC535  22U_0603_6.3V6M  [C_0603]  185.3 123.71 270 top
PC536  22U_0603_6.3V6M  [C_0603]  185.78 129.83 90 top
PC537  1000P_0603_50V7K  [C_0603]  165.53 136.56 0 top
PC538  1000P_0603_50V7K  [C_0603]  178.1 129.28 270 top
PC539  0.047U_0402_25V7K  [C_0402]  168.13 127.92 90 top
PC540  10U_0805_25V6K  [C_0805]  176.4 114.31 180 top
PC541  0.1U_0402_25V7K  [C_0402]  176.22 112.93 180 top
PC542  0.1U_0402_25V6  [C_0402]  177.46 118.96 270 top
PC543  22U_0603_6.3V6M  [C_0603]  190.86 111.98 90 top
PC544  22U_0603_6.3V6M  [C_0603]  180.13 110.9 180 top
PC545  22U_0603_6.3V6M  [C_0603]  191.37 109.95 270 top
PC546  22U_0603_6.3V6M  [C_0603]  180.13 107.86 180 top
PC547  22U_0603_6.3V6M  [C_0603]  190.15 109.95 270 top
PC548  1000P_0603_50V7K  [C_0603]  186.92 114.59 0 top
PC549  0.047U_0402_25V7K  [C_0402]  174.83 119.93 270 top
PC550  10U_0805_25V6K  [C_0805]  180.28 109.38 180 top
PC551  10U_0805_25V6K  [C_0805]  188.58 110.1 270 top
PC552  2200P_0402_50V7K  [C_0402]  163.18 113.52 270 top
PC553  2200P_0402_50V7K  [C_0402]  179.18 135.54 90 top
PC554  2200P_0402_50V7K  [C_0402]  177.53 111.1 270 top
PC555  2200P_0402_50V7K  [C_0402]  173.88 126.03 90 top
PC556  2200P_0402_50V7K  [C_0402]  167.67 130.59 0 top
PC557  22U_0603_6.3V6M  [C_0603]  181.53 121.09 270 top
PC558  22U_0603_6.3V6M  [C_0603]  180.26 121.09 270 top
PC559  10U_0603_25V6M  [C_0603]  181.21 135.48 90 top
PC560  10U_0603_25V6M  [C_0603]  182.48 135.48 90 top
PC561  10U_0603_25V6M  [C_0603]  176.21 110.63 180 top
PC562  10U_0603_25V6M  [C_0603]  176.21 111.9 180 top
PC563  22U_0603_6.3V6M  [C_0603]  187.05 109.95 270 top
PC564  22U_0603_6.3V6M  [C_0603]  187.05 111.98 90 top
PC565  22U_0603_6.3V6M  [C_0603]  188.32 111.98 90 top
PC566  22U_0603_6.3V6M  [C_0603]  189.59 111.98 90 top
PC567  10P_0201_25V8  [C_0201]  181.78 118.61 180 top
PC600  10U_0603_25V6M  [C_0603]  171.81 130.21 0 top
PC601  0.1U_0402_25V7K  [C_0402]  169.65 130.54 270 top
PC602  10U_0603_25V6M  [C_0603]  168.89 118.02 90 top
PC603  0.1U_0402_25V7K  [C_0402]  167.87 118.52 180 top
PC604  1U_0402_16V6K  [C_0402]  169.65 127.85 90 top
PC605  0.1U_0402_25V6  [C_0402]  171.75 117.79 180 top
PC606  1000P_0603_50V7K  [C_0603]  171.3 133.51 0 top
PC607  1U_0402_16V6K  [C_0402]  172.12 126.08 90 top
PC608  0.1U_0402_25V6  [C_0402]  171.43 127.9 90 top
PC609  22U_0603_6.3V6M  [C_0603]  177.02 133 0 top
PC610  22U_0603_6.3V6M  [C_0603]  173.97 134.15 90 top
PC611  22U_0603_6.3V6M  [C_0603]  177.02 131.8 0 top
PC612  22U_0603_6.3V6M  [C_0603]  169.84 112.05 0 top
PC613  22U_0603_6.3V6M  [C_0603]  167.75 112.05 180 top
PC614  22U_0603_6.3V6M  [C_0603]  167.75 113.32 180 top
PC615  22U_0603_6.3V6M  [C_0603]  169.84 113.32 0 top
PC616  1000P_0603_50V7K  [C_0603]  172.32 113.44 270 top
PC617  1U_0402_16V6K  [C_0402]  161.91 122.33 270 top
PC618  10U_0805_25V6K  [C_0805]  160.17 126.63 270 top
PC619  0.1U_0402_25V7K  [C_0402]  158.01 126.59 270 top
PC620  0.1U_0402_25V6  [C_0402]  161.44 126.27 0 top
PC621  10U_0603_10V6M  [C_0603]  162.15 132.51 90 top
PC622  22U_0603_6.3V6M  [C_0603]  154.27 119.92 0 top
PC623  22U_0603_6.3V6M  [C_0603]  151.7 125.71 90 top
PC624  22U_0603_6.3V6M  [C_0603]  152.89 125.71 90 top
PC625  22U_0603_6.3V6M  [C_0603]  151.9 120.2 270 top
PC626  22U_0603_6.3V6M  [C_0603]  153.14 120.2 270 top
PC627  22U_0603_6.3V6M  [C_0603]  150.65 120.2 270 top
PC628  22U_0603_6.3V6M  [C_0603]  150.5 125.71 90 top
PC629  1000P_0603_50V7K  [C_0603]  150.6 129.95 270 top
PC630  0.047U_0402_25V7K  [C_0402]  161.4 130.69 90 top
PC631  22U_0603_6.3V6M  [C_0603]  161.27 135.03 90 top
PC632  22U_0603_6.3V6M  [C_0603]  162.54 135.03 90 top
PC633  0.22U_0402_10V4Z  [C_0402]  163.24 133.46 270 top
PC634  1U_0402_16V6K  [C_0402]  162.79 122.33 270 top
PC635  10U_0805_25V6K  [C_0805]  160.49 110.59 0 top
PC636  0.1U_0402_25V7K  [C_0402]  159.49 112.74 270 top
PC637  0.1U_0402_25V6  [C_0402]  163.56 106.51 90 top
PC638  22U_0603_6.3V6M  [C_0603]  151.81 104.49 180 top
PC639  22U_0603_6.3V6M  [C_0603]  151.81 108.3 180 top
PC640  22U_0603_6.3V6M  [C_0603]  151.81 107.03 180 top
PC641  22U_0603_6.3V6M  [C_0603]  151.81 105.76 180 top
PC642  22U_0603_6.3V6M  [C_0603]  151.81 109.57 180 top
PC643  1000P_0603_50V7K  [C_0603]  161.52 104.43 0 top
PC644  0.047U_0402_25V7K  [C_0402]  165.08 117.56 270 top
PC645  2200P_0402_50V7K  [C_0402]  170.8 130.59 270 top
PC646  2200P_0402_50V7K  [C_0402]  158.87 126.59 270 top
PC648  2200P_0402_50V7K  [C_0402]  158.36 110.65 180 top
PC649  2200P_0402_50V7K  [C_0402]  167.87 119.41 180 top
PC700  10U_0805_25V6K  [C_0805]  177.02 122.68 270 top
PC701  0.1U_0402_25V6  [C_0402]  179.23 120.4 180 top
PC702  1U_0402_6.3V6K  [C_0402]  162.87 119.92 180 top
PC703  1U_0402_6.3V6K  [C_0402]  174.83 122.84 270 top
PC704  1U_0402_6.3V6K  [C_0402]  163.3 128.94 180 top
PC705  1U_0402_6.3V6K  [C_0402]  175.72 122.84 270 top
PC706  1U_0402_6.3V6K  [C_0402]  172.22 120.23 0 top
PC707  1U_0402_6.3V6K  [C_0402]  163.3 128.05 180 top
PC708  4.7U_0603_6.3V6M  [C_0603]  174.29 128.43 180 top
PC709  1U_0402_6.3V6K  [C_0402]  173.97 121.09 270 top
PC710  4.7U_0603_6.3V6M  [C_0603]  172.9 122.78 270 top
PC711  1U_0402_6.3V6K  [C_0402]  175.75 121.06 180 top
PC712  0.1U_0201_10V6K  [C_0201]  176.04 124.75 180 top
PC713  0.1U_0201_10V6K  [C_0201]  172.83 125.17 270 top
PC714  0.1U_0402_25V6  [C_0402]  172.6 116.48 90 top
PC715  1U_0402_6.3V6K  [C_0402]  175.18 116.9 0 top
PC716  1U_0402_6.3V6K  [C_0402]  158.96 130.46 0 top
PC717  1U_0402_16V6K  [C_0402]  175.74 118.14 180 top
PC718  0.1U_0402_25V6  [C_0402]  184.56 135.67 0 top
PC800  1U_0402_16V6K  [C_0402]  69.02 108.24 180 top
PC801  1U_0402_16V6K  [C_0402]  71.67 113.88 90 top
PC802  1U_0402_16V6K  [C_0402]  75.55 109.77 270 top
PC803  1U_0402_16V6K  [C_0402]  86.47 104.12 270 top
PC804  0.47U_0402_25V6K  [C_0402]  82.01 104.86 0 top
PC806  1000P_0603_50V7K  [C_0603]  87.17 114.21 0 top
PC807  0.1U_0402_25V6  [C_0402]  77.39 112.03 90 top
PC808  1000P_0402_25V8J  [C_0402]  67.1 109.14 270 top
PC809  390P_0402_50V7K  [C_0402]  76.08 115.69 0 top
PC810  150P_0402_50V8J  [C_0402]  77.15 113.89 180 top
PC811  22P_0402_50V8J  [C_0402]  77.15 114.78 180 top
PC812  150P_0402_50V8J  [C_0402]  78.76 115.68 90 top
PC813  100P_0402_50V8J  [C_0402]  67.04 115.31 90 top
PC814  47U_0603_6.3V6M  [C_0603]  108.55 100.55 0 top
PC817  10U_0805_25V6K  [C_0805]  80.98 117.55 270 top
PC818  33U_B3_16VM_R45M  [C_B3]  79.74 119.54 90 top
PC820  10U_0805_25V6K  [C_0805]  81.43 108.05 270 top
PC821  33U_B3_16VM_R45M  [C_B3]  78.89 108.58 270 top
PC822  2200P_0402_25V7K  [C_0402]  81.26 109.3 90 top
PC823  0.1U_0402_25V7K  [C_0402]  82.15 109.3 90 top
PC824  33U_B3_16VM_R45M  [C_B3]  68.01 98.46 270 top
PC900  1U_0402_16V6K  [C_0402]  85.71 114.77 90 top
PC901  0.47U_0402_25V6K  [C_0402]  82.28 114.89 90 top
PC903  1000P_0603_50V7K  [C_0603]  84.91 124.87 180 top
PC904  0.1U_0402_25V6  [C_0402]  70.8 115.67 180 top
PC905  390P_0402_50V7K  [C_0402]  73.45 115.91 90 top
PC906  22P_0402_50V8J  [C_0402]  72.56 116.82 270 top
PC907  150P_0402_50V8J  [C_0402]  72.57 118.59 180 top
PC908  150P_0402_50V8J  [C_0402]  71.67 116.82 270 top
PC909  100P_0402_50V8J  [C_0402]  68.94 115.31 90 top
PC910  0.1U_0402_25V7K  [C_0402]  79.69 117.36 270 top
PC911  2200P_0402_25V7K  [C_0402]  81.77 120.23 90 top
PC912  22U_0603_6.3V6M  [C_0603]  93.99 114.89 270 top
PC1000  0.47U_0402_25V6K  [C_0402]  80.37 102.73 270 top
PC1002  1U_0402_16V6K  [C_0402]  71.99 107.3 270 top
PC1003  1000P_0603_50V7K  [C_0603]  84.25 102.14 0 top
PC1004  0.068U_0402_16V7K  [C_0402]  69.02 104.68 180 top
PC1005  330P_0402_50V7K  [C_0402]  67.1 105.52 270 top
PC1006  220P_0402_50V7K  [C_0402]  65.31 102.84 0 top
PC1007  22P_0402_50V8J  [C_0402]  67.1 103.74 270 top
PC1008  150P_0402_50V8J  [C_0402]  69.02 103.79 180 top
PC1009  100P_0402_50V8J  [C_0402]  68.01 101.14 0 top
PC1010  1000P_0402_25V8J  [C_0402]  69.02 109.13 180 top
PC1013  0.1U_0402_25V7K  [C_0402]  73.13 97.01 270 top
PC1014  2200P_0402_25V7K  [C_0402]  74.02 97.01 270 top
PC1015  47U_0603_6.3V6M  [C_0603]  127.9 95.02 180 top
PC1017  10U_0805_25V6K  [C_0805]  76.75 101.85 90 top
PC1018  10U_0805_25V6K  [C_0805]  75.03 101.85 90 top
PC1100  0.1U_0201_6.3V6K  [C_0201]  120.15 107.25 90 bottom
PC1101  0.1U_0201_6.3V6K  [C_0201]  122.36 104.76 90 bottom
PC1102  0.1U_0201_6.3V6K  [C_0201]  122.94 107.27 90 bottom
PC1103  0.1U_0201_6.3V6K  [C_0201]  118.42 106.04 90 bottom
PC1104  0.1U_0201_6.3V6K  [C_0201]  121.24 106.05 90 bottom
PC1105  0.1U_0201_6.3V6K  [C_0201]  122.92 104.76 90 bottom
PC1106  0.1U_0201_6.3V6K  [C_0201]  119.01 107.26 90 bottom
PC1107  0.1U_0201_6.3V6K  [C_0201]  119.56 107.25 90 bottom
PC1108  0.1U_0201_6.3V6K  [C_0201]  121.8 106.05 90 bottom
PC1109  0.1U_0201_6.3V6K  [C_0201]  122.92 106.05 90 bottom
PC1110  0.1U_0201_6.3V6K  [C_0201]  123.64 105.44 0 bottom
PC1111  0.1U_0201_6.3V6K  [C_0201]  123.64 107.68 0 bottom
PC1112  0.1U_0201_6.3V6K  [C_0201]  124.29 100.07 270 bottom
PC1113  0.1U_0201_6.3V6K  [C_0201]  123.67 104.3 0 bottom
PC1114  0.1U_0201_6.3V6K  [C_0201]  123.64 102.07 0 bottom
PC1115  0.1U_0201_6.3V6K  [C_0201]  126.69 100.36 0 bottom
PC1116  0.1U_0201_6.3V6K  [C_0201]  126.69 106.89 0 bottom
PC1117  0.1U_0201_6.3V6K  [C_0201]  126.69 106.33 0 bottom
PC1118  0.1U_0201_6.3V6K  [C_0201]  126.69 103.59 0 bottom
PC1119  0.1U_0201_6.3V6K  [C_0201]  126.69 102.98 0 bottom
PC1120  0.1U_0201_6.3V6K  [C_0201]  121.27 107.26 90 bottom
PC1121  0.1U_0201_6.3V6K  [C_0201]  120.68 106.05 90 bottom
PC1122  0.1U_0201_6.3V6K  [C_0201]  122.41 103.54 90 bottom
PC1123  0.1U_0201_6.3V6K  [C_0201]  122.36 106.05 90 bottom
PC1124  0.1U_0201_6.3V6K  [C_0201]  118.98 104.77 90 bottom
PC1125  0.1U_0201_6.3V6K  [C_0201]  126.69 102.32 0 bottom
PC1126  0.1U_0201_6.3V6K  [C_0201]  126.69 104.17 0 bottom
PC1127  0.1U_0201_6.3V6K  [C_0201]  123.68 100.07 270 bottom
PC1128  0.1U_0201_6.3V6K  [C_0201]  123.07 100.07 270 bottom
PC1129  0.1U_0201_6.3V6K  [C_0201]  122.46 100.07 270 bottom
PC1130  0.1U_0201_6.3V6K  [C_0201]  121.24 100.07 270 bottom
PC1131  0.1U_0201_6.3V6K  [C_0201]  121.85 100.07 270 bottom
PC1132  0.1U_0201_6.3V6K  [C_0201]  126.69 107.45 0 bottom
PC1133  0.1U_0201_6.3V6K  [C_0201]  126.69 101.68 0 bottom
PC1134  0.1U_0201_6.3V6K  [C_0201]  123.64 106 0 bottom
PC1135  0.1U_0201_6.3V6K  [C_0201]  122.38 107.27 90 bottom
PC1136  0.1U_0201_6.3V6K  [C_0201]  119.56 106.04 90 bottom
PC1137  0.1U_0201_6.3V6K  [C_0201]  123.64 103.74 0 bottom
PC1138  0.1U_0201_6.3V6K  [C_0201]  123.64 102.62 0 bottom
PC1139  0.1U_0201_6.3V6K  [C_0201]  126.69 101 0 bottom
PC1140  0.1U_0201_6.3V6K  [C_0201]  123.64 106.56 0 bottom
PC1141  0.1U_0201_6.3V6K  [C_0201]  123.64 107.12 0 bottom
PC1142  0.1U_0201_6.3V6K  [C_0201]  126.69 105.77 0 bottom
PC1143  0.1U_0201_6.3V6K  [C_0201]  126.69 105.06 0 bottom
PC1144  0.1U_0201_6.3V6K  [C_0201]  123.64 104.88 0 bottom
PC1145  0.1U_0201_6.3V6K  [C_0201]  120.63 100.07 270 bottom
PC1146  0.1U_0201_6.3V6K  [C_0201]  120.02 100.07 270 bottom
PC1147  0.1U_0201_6.3V6K  [C_0201]  123.67 101.48 180 bottom
PC1148  0.1U_0201_6.3V6K  [C_0201]  123.64 103.18 0 bottom
PC1151  1U_0201_6.3V6M  [C_0201]  112.31 103.94 90 top
PC1152  1U_0201_6.3V6M  [C_0201]  111.74 103.94 90 top
PC1155  47U_0603_6.3V6M  [C_0603]  111.45 103.02 270 top
PC1156  10U_0402_6.3V6M  [C_0402]  113.95 104.45 180 top
PC1157  10U_0402_6.3V6M  [C_0402]  110.85 98.59 270 top
PC1158  10U_0402_6.3V6M  [C_0402]  112.63 99.78 90 top
PC1159  10U_0402_6.3V6M  [C_0402]  113.52 99.78 90 top
PC1160  10U_0402_6.3V6M  [C_0402]  111.74 98.59 270 top
PC1161  10U_0402_6.3V6M  [C_0402]  111.74 99.78 90 top
PC1162  10U_0402_6.3V6M  [C_0402]  112.63 98.59 270 top
PC1163  10U_0402_6.3V6M  [C_0402]  113.49 98.59 270 top
PC1164  10U_0402_6.3V6M  [C_0402]  110.85 99.78 90 top
PC1165  0.1U_0201_6.3V6K  [C_0201]  122.97 103.54 90 bottom
PC1166  47U_0603_6.3V6M  [C_0603]  93.97 118.93 0 top
PC1167  47U_0603_6.3V6M  [C_0603]  113.2 102.97 270 top
PC1168  47U_0603_6.3V6M  [C_0603]  114.41 102.97 270 top
PC1169  47U_0603_6.3V6M  [C_0603]  93.97 120.2 0 top
PC1170  47U_0603_6.3V6M  [C_0603]  93.97 117.66 0 top
PC1171  47U_0603_6.3V6M  [C_0603]  110.24 103.03 270 top
PC1172  47U_0603_6.3V6M  [C_0603]  109.04 103.03 270 top
PC1173  47U_0603_6.3V6M  [C_0603]  92.77 114.89 270 top
PC1174  47U_0603_6.3V6M  [C_0603]  107.83 103.03 270 top
PC1175  47U_0603_6.3V6M  [C_0603]  110.85 103.98 90 top
PC1176  47U_0603_6.3V6M  [C_0603]  91.55 105.38 270 top
PC1177  47U_0603_6.3V6M  [C_0603]  100.29 101.84 90 top
PC1178  47U_0603_6.3V6M  [C_0603]  107.6 100.55 180 top
PC1179  47U_0603_6.3V6M  [C_0603]  101.99 100.03 180 top
PC1180  47U_0603_6.3V6M  [C_0603]  103.77 98.99 270 top
PC1181  47U_0603_6.3V6M  [C_0603]  106.19 98.99 270 top
PC1182  47U_0603_6.3V6M  [C_0603]  90.28 105.38 270 top
PC1183  47U_0603_6.3V6M  [C_0603]  92.82 105.38 270 top
PC1184  47U_0603_6.3V6M  [C_0603]  104.97 98.99 270 top
PC1185  47U_0603_6.3V6M  [C_0603]  107.41 99 270 top
PC1186  47U_0603_6.3V6M  [C_0603]  109.65 103.98 90 top
PC1187  47U_0603_6.3V6M  [C_0603]  100.27 105.58 270 top
PC1188  47U_0603_6.3V6M  [C_0603]  93.97 121.47 0 top
PC1189  1U_0201_6.3V6M  [C_0201]  127.88 101.33 0 bottom
PC1190  0.1U_0201_6.3V6K  [C_0201]  127.91 106.23 0 bottom
PC1191  0.1U_0201_6.3V6K  [C_0201]  127.88 104.4 0 bottom
PC1192  0.1U_0201_6.3V6K  [C_0201]  127.88 103.13 0 bottom
PC1193  0.1U_0201_6.3V6K  [C_0201]  127.91 107.4 0 bottom
PC1194  22U_0603_6.3V6M  [C_0603]  105.09 96.29 270 top
PC1195  22U_0603_6.3V6M  [C_0603]  82.53 94.86 270 top
PC1196  4.7U_0603_25V6K  [C_0603]  86.34 94.86 270 top
PC1197  22U_0603_6.3V6M  [C_0603]  136.34 89.64 270 top
PC1198  22U_0603_6.3V6M  [C_0603]  135.12 89.64 270 top
PC1199  22U_0603_6.3V6M  [C_0603]  83.8 94.86 270 top
PC1200  22U_0603_6.3V6M  [C_0603]  85.07 94.86 270 top
PC1201  22U_0603_6.3V6M  [C_0603]  107.52 96.31 270 top
PC1202  47U_0603_6.3V6M  [C_0603]  127.9 93.82 180 top
PC1203  22U_0603_6.3V6M  [C_0603]  106.31 96.29 270 top
PC1204  0.1U_0201_6.3V6K  [C_0201]  120.12 106.05 90 bottom
PC1205  47U_0603_6.3V6M  [C_0603]  109.81 98.94 270 top
PC1206  47U_0603_6.3V6M  [C_0603]  108.6 98.92 270 top
PC1207  47U_0603_6.3V6M  [C_0603]  108.44 103.98 90 top
PC1208  47U_0603_6.3V6M  [C_0603]  101.43 107.93 180 top
PC1209  47U_0603_6.3V6M  [C_0603]  101.43 106.66 180 top
PC1210  0.1U_0201_6.3V6K  [C_0201]  127.88 102.5 0 bottom
PC1211  0.1U_0201_6.3V6K  [C_0201]  127.88 101.91 0 bottom
PC1212  0.1U_0201_6.3V6K  [C_0201]  127.88 103.77 0 bottom
PC1213  0.1U_0201_6.3V6K  [C_0201]  127.88 105.04 0 bottom
PC1214  0.1U_0201_6.3V6K  [C_0201]  127.91 105.6 0 bottom
PC1215  0.1U_0201_6.3V6K  [C_0201]  127.91 106.84 0 bottom
PC1216  0.1U_0201_6.3V6K  [C_0201]  119.03 103.55 90 bottom
PC1217  0.1U_0201_6.3V6K  [C_0201]  118.45 103.55 90 bottom
PC1218  0.1U_0201_6.3V6K  [C_0201]  120.17 101.56 270 bottom
PC1219  0.1U_0201_6.3V6K  [C_0201]  120.76 101.56 270 bottom
PC1220  0.1U_0201_6.3V6K  [C_0201]  118.42 104.75 90 bottom
PC1221  0.1U_0201_6.3V6K  [C_0201]  119.59 103.55 90 bottom
PC1222  0.1U_0201_6.3V6K  [C_0201]  119.61 101.54 270 bottom
PC1223  0.1U_0201_6.3V6K  [C_0201]  122.51 101.56 270 bottom
PC1224  0.1U_0201_6.3V6K  [C_0201]  120.17 103.55 90 bottom
PC1225  0.1U_0201_6.3V6K  [C_0201]  121.85 102.85 270 bottom
PC1226  0.1U_0201_6.3V6K  [C_0201]  122.41 102.85 270 bottom
PC1227  0.1U_0201_6.3V6K  [C_0201]  121.8 104.76 90 bottom
PC1228  0.1U_0201_6.3V6K  [C_0201]  118.47 102.84 270 bottom
PC1229  0.1U_0201_6.3V6K  [C_0201]  120.17 102.85 270 bottom
PC1230  0.1U_0201_6.3V6K  [C_0201]  120.73 102.85 270 bottom
PC1231  0.1U_0201_6.3V6K  [C_0201]  119.56 104.76 90 bottom
PC1232  0.1U_0201_6.3V6K  [C_0201]  120.12 104.76 90 bottom
PC1233  0.1U_0201_6.3V6K  [C_0201]  121.34 101.56 270 bottom
PC1234  0.1U_0201_6.3V6K  [C_0201]  121.93 101.56 270 bottom
PC1235  0.1U_0201_6.3V6K  [C_0201]  119.06 101.54 270 bottom
PC1236  0.1U_0201_6.3V6K  [C_0201]  121.29 102.85 270 bottom
PC1237  0.1U_0201_6.3V6K  [C_0201]  120.68 104.76 90 bottom
PC1238  0.1U_0201_6.3V6K  [C_0201]  121.24 104.76 90 bottom
PC1239  0.1U_0201_6.3V6K  [C_0201]  121.82 107.26 90 bottom
PC1240  0.1U_0201_6.3V6K  [C_0201]  120.73 103.54 90 bottom
PC1241  0.1U_0201_6.3V6K  [C_0201]  121.29 103.54 90 bottom
PC1242  0.1U_0201_6.3V6K  [C_0201]  121.85 103.54 90 bottom
PC1243  0.1U_0201_6.3V6K  [C_0201]  119.06 102.84 270 bottom
PC1244  0.1U_0201_6.3V6K  [C_0201]  119.61 102.84 270 bottom
PC1245  10U_0603_25V6M  [C_0603]  75.61 110.97 0 top
PC1246  0.1U_0201_6.3V6K  [C_0201]  118.45 107.26 90 bottom
PC1247  0.1U_0201_6.3V6K  [C_0201]  119.01 106.04 90 bottom
PC1248  0.1U_0201_6.3V6K  [C_0201]  122.97 102.85 270 bottom
PC1249  0.1U_0201_6.3V6K  [C_0201]  120.71 107.25 90 bottom
PC1250  10U_0402_6.3V6M  [C_0402]  104.03 99.94 0 top
PC1251  10U_0402_6.3V6M  [C_0402]  93.83 105.93 0 top
PC1252  10U_0402_6.3V6M  [C_0402]  93.83 105.04 0 top
PC1253  22U_0603_6.3V6M  [C_0603]  108.77 96.32 270 top
PC1254  22U_0603_6.3V6M  [C_0603]  109.99 96.34 270 top
PD100  -  [TVNST52302AB0_SOT523-3]  159.37 94.59 0 top
PD101  -  [TVNST52302AB0_SOT523-3]  161.65 94.59 0 top
PD102  -  [RB520SM-30T2R_EMD2-2]  45.95 111.5 90 top
PD103  -  [RB520SM-30T2R_EMD2-2]  46.88 134.02 0 top
PD104  -  [RB520SM-30T2R_EMD2-2]  46.88 132.75 0 top
PD105  -  [RB520SM-30T2R_EMD2-2]  33.45 64.8 270 top
PD106  -  [RB520SM-30T2R_EMD2-2]  34.68 64.8 270 top
PD107  -  [RB520SM-30T2R_EMD2-2]  32.24 64.8 270 top
PD108  -  [RB520SM-30T2R_EMD2-2]  30.97 64.8 270 top
PD201  -  [RB520SM-30T2R_EMD2-2]  51.23 146.43 270 top
PD202  -  [RB520SM-30T2R_EMD2-2]  50.01 146.43 270 top
PD203  -  [PD3S230L-7_POWERDI323-2]  72.03 136.08 270 top
PD204  -  [RB520SM-30T2R_EMD2-2]  67.2 118.11 0 top
PD205  -  [RB520SM-30T2R_EMD2-2]  95.68 96.26 270 top
PD301  -  [RB520SM-30T2R_EMD2-2]  165.35 100.54 180 top
PD302  -  [RB520SM-30T2R_EMD2-2]  166.76 102.29 90 top
PD400  -  [RB520SM-30T2R_EMD2-2]  58.82 137.37 180 top
PD401  -  [RB520SM-30T2R_EMD2-2]  58.81 136.04 180 top
PD402  -  [RB520SM-30T2R_EMD2-2]  54.79 135.98 90 top
PD403  -  [RB520SM-30T2R_EMD2-2]  55.99 135.98 90 top
PH800  10K_0402_5%_B25/50 4250K  [R_0402]  91.48 113.08 270 top
PH900  10K_0402_5%_B25/50 4250K  [R_0402]  91.04 124.21 270 top
PH1000  10KB_0402_5%_ERTJ0ER103J  [R_0402]  80.3 93.89 0 top
PH1001  100K_0402_1%_TSM0B104F4251RZ  [R_0402]  78.04 101.89 0 top
PH1002  100K_0402_1%_TSM0B104F4251RZ  [R_0402]  86.9 116.37 0 top
PH1003  100K_0402_1%_TSM0B104F4251RZ  [R_0402]  87.92 105.06 0 top
PJP500  -  [JUMP_43X79]  151.07 112.17 0 top
PJP501  -  [JUMP_43X39]  183.23 119.27 270 top
PJP502  -  [JUMP_43X118]  188.58 123.05 90 top
PJP503  -  [JUMP_43X39]  171.56 135.29 0 top
PJP504  -  [JUMP_43X118]  183.5 107.22 90 top
PJP600  -  [JUMP_43X39]  175.88 135.31 270 top
PJP601  -  [JUMP_43X39]  165.59 110.32 180 top
PJP602  -  [JUMP_43X79]  152.41 123.1 0 bottom
PJP603  -  [JUMP_43X79]  154.79 103.42 90 top
PL100  HCB2012KF-121T50_0805  [TAI-T_HCB2012KF-121T50_2P]  41.68 103.17 90 top
PL101  HCB2012KF-121T50_0805  [TAI-T_HCB2012KF-121T50_2P]  48.72 103.16 90 top
PL400  HCB2012KF-121T50_0805  [TAI-T_HCB2012KF-121T50_2P]  49.65 117.6 90 top
PL401  1UH_PCME061E-1R0MS_5.5A_20%  [CYNTE_PCME061E-1R0MS_2P]  55.61 112.3 270 top
PL500  HCB2012KF-121T50_0805  [TAI-T_HCB2012KF-121T50_2P]  176.36 125.79 90 top
PL501  HCB2012KF-121T50_0805  [TAI-T_HCB2012KF-121T50_2P]  156.35 111.93 0 top
PL502  1UH_PCMB041B-1R0MS_4.2A_20%  [CYNTE_PCMB041B-1R0MS_2P]  154.35 115.16 0 top
PL503  1UH_1239AS-H-1R0M-P2_3A_20%  [TOKO_1239AS-H-1R0M-P2_2P]  179.69 122.93 0 top
PL504  HCB2012KF-121T50_0805  [TAI-T_HCB2012KF-121T50_2P]  165.97 129.99 90 top
PL505  HCB2012KF-121T50_0805  [TAI-T_HCB2012KF-121T50_2P]  177.81 136.67 270 top
PL506  0.47UH_MMD-04AE-R47M-M1L_8A_20%  [MAG_MMD-04AE-R47M-M1L_2P]  182.73 125.46 90 top
PL507  2.2UH_1239AS-H-2R2N-P2_1.3A_30%  [TOKO_1239AS-H-2R2N-P2_2P]  165.72 134.02 0 top
PL508  HCB2012KF-121T50_0805  [TAI-T_HCB2012KF-121T50_2P]  179.52 112.49 180 top
PL509  0.47UH_MMD-05ABHR47M-T1L_7A_20%  [MAG_MMD-05ABHR47M-T1L_2P]  183.52 111.49 90 top
PL600  HCB2012KF-121T50_0805  [TAI-T_HCB2012KF-121T50_2P]  167.51 131.99 0 top
PL601  HCB2012KF-121T50_0805  [TAI-T_HCB2012KF-121T50_2P]  167.24 117.38 270 top
PL602  2.2UH_1239AS-H-2R2N-P2_1.3A_30%  [TOKO_1239AS-H-2R2N-P2_2P]  175.88 132.37 180 top
PL603  2.2UH_1239AS-H-2R2N-P2_1.3A_30%  [TOKO_1239AS-H-2R2N-P2_2P]  169.27 116.62 270 top
PL604  HCB2012KF-121T50_0805  [TAI-T_HCB2012KF-121T50_2P]  160.28 128.19 180 top
PL605  0.47UH_MMD-04AB-R47M-V2_6A_20%  [MAG_MMD-04AB-R47M-V2_2P]  153.36 122.94 0 top
PL607  0.47UH_MMD-04AB-R47M-V2_6A_20%  [MAG_MMD-04AB-R47M-V2_2P]  155.05 107.86 0 top
PL802  0.22UH_PIME051E-R22MS3R805_16A_20%  [CYNTE_PIME051E-R22MS3R805_2P]  87.72 108.87 0 top
PL902  0.22UH_PIME051E-R22MS3R805_16A_20%  [CYNTE_PIME051E-R22MS3R805_2P]  87.34 120.05 0 top
PL1001  0.47UH_MMD-05ABHR47MET1L_7A_20%  [MAG_MMD-05ABHR47MET1L_2P]  80.29 98.46 0 top
PQ100  -  [AON7405_DFN8-5]  41.94 107.96 0 top
PQ101  -  [AON7405_DFN8-5]  43.91 115.57 180 top
PQ103  -  [SI2303CDS-T1-GE3_SOT23-3]  47.59 120.66 0 top
PQ104  -  [DMN66D0LDW-7_SOT363-6]  43.28 125.63 0 top
PQ105  -  [SI2303CDS-T1-GE3_SOT23-3]  43.9 94.46 270 top
PQ107  -  [AON7405_DFN8-5]  47.38 107.7 0 top
PQ108  -  [AON7405_DFN8-5]  49.38 115.31 180 top
PQ109  -  [DMN66D0LDW-7_SOT363-6]  45.89 129.18 90 top
PQ110  -  [DMN66D0LDW-7_SOT363-6]  47.11 128.14 180 top
PQ111  -  [DCX124EU-7-F_SOT363-6]  43.15 123.71 270 top
PQ112  -  [DCX124EU-7-F_SOT363-6]  43.18 120.88 270 top
PQ113  -  [AO3413_SOT23-3]  43.63 89.53 90 top
PQ114  -  [AO3413_SOT23-3]  24.96 90.47 180 top
PQ115  -  [DMN66D0LDW-7_SOT363-6]  39.49 90.66 180 top
PQ120  -  [DMN66D0LDW-7_SOT363-6]  41.72 95.69 180 top
PQ202  -  [AON7405_DFN8-5]  73.92 138.5 0 top
PQ203  -  [AON7405_DFN8-5]  68.92 138.5 0 top
PQ204  -  [DMN66D0LDW-7_SOT363-6]  67.23 139.97 180 top
PQ205  -  [DMN66D0LDW-7_SOT363-6]  59.85 139.72 90 top
PQ206  -  [DMN66D0LDW-7_SOT363-6]  56.52 144.96 0 top
PQ207  -  [AON7405_DFN8-5]  75.9 136.67 180 top
PQ208  -  [AON7405_DFN8-5]  70.39 136.67 180 top
PQ209  -  [AO3413_SOT23-3]  53.96 143.87 0 top
PQ210  S TR 2N7002KW 1N SOT323-3  [SSM3K7002FU_SC70-3]  58.23 147.87 270 top
PQ211  -  [AO3413_SOT23-3]  55.93 140.16 90 top
PQ212  -  [SI2336DS-T1-GE3_SOT23-3]  173.59 106.95 270 top
PQ214  -  [DMN66D0LDW-7_SOT363-6]  76.62 123.6 180 top
PQ300  -  [DMN65D8LW-7_SOT323-3]  170.86 108.68 180 top
PQ400  AON7934_DFN3X3A-8-10  [AON7934_DFN3X3A8-10]  56.18 117.01 270 top
PQ401  -  [AON7405_DFN8-5]  74.24 87.76 270 top
PQ402  -  [DMN66D0LDW-7_SOT363-6]  52.34 135.77 0 top
PQ500  AON7934_DFN3X3A-8-10  [AON7934_DFN3X3A8-10]  160.89 114.97 0 top
PQ501  AON7934_DFN3X3A-8-10  [AON7934_DFN3X3A8-10]  181.46 133.76 270 top
PQ502  AON7934_DFN3X3A-8-10  [AON7934_DFN3X3A8-10]  177.78 114.21 0 top
